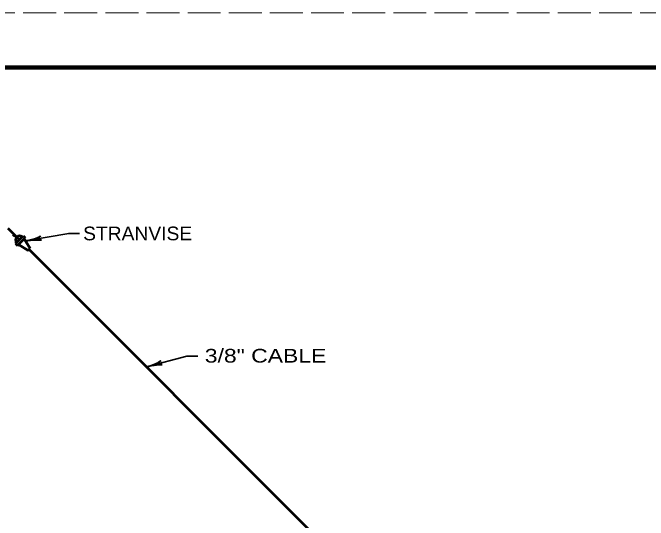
# Model space of a CAD drawing. Extents: x 12366 to 13046, y 9129 to 9570.
# Drawn here: x 12746.6 to 12862.5, y 9477.1 to 9569.5 of the extents above; entities that cross this region are included whole.
import ezdxf

# ---------------------------------------------------------------- set-up
doc = ezdxf.new("R2010")
doc.units = 0
doc.linetypes.add('LONG_DASHED', pattern=[7.5, 6, -1.5])
doc.layers.add('1', color=7, linetype='Continuous', lineweight=53)
doc.layers.add('61', color=7, linetype='Continuous', lineweight=35)

msp = doc.modelspace()

# ---------------------------------------------------------------- linework, layer by layer
at = {"layer": '1'}
for p, q in [((12745.687, 9530.302), (12747.808, 9528.181)), ((12747.324, 9528.665), (12746.62, 9529.072)), ((12747.101, 9527.474), (12748.515, 9528.888)), ((12747.455, 9527.12), (12748.869, 9528.534)), ((12748.515, 9528.888), (12748.869, 9528.534)), ((12748.692, 9528.358), (12749.753, 9526.59)), ((12747.101, 9527.474), (12747.455, 9527.12)), ((12747.631, 9527.297), (12749.399, 9526.236)), ((12749.399, 9526.236), (12749.753, 9526.59)), ((12749.576, 9526.413), (12810.747, 9465.242))]:
    msp.add_line(p, q, dxfattribs=at)
at = {"layer": '1', "lineweight": 35}
for points in [[(12748.934, 9527.954), (12756.791, 9529.339), (12758.791, 9529.339)], [(12770.977, 9505.011), (12778.337, 9506.983), (12780.337, 9506.983)]]:
    msp.add_lwpolyline(points, dxfattribs=at)
at = {"layer": '1'}
msp.add_arc((12747.856, 9528.133), 0.753, 50.20411, 219.79589, dxfattribs=at)
at = {"layer": '1', "lineweight": 40}
for centre, major_axis, ratio, start_param, end_param in [((12749.961, 9528.416), (-1.731, -0.464), 0.122415, 0.8963533, 3.1415927), ((12750.074, 9527.94), (1.76, 0.132), 0.07063, 6.2823074, 8.5597026), ((12771.96, 9505.561), (-1.684, -0.613), 0.122415, 0.8963533, 3.1415927), ((12771.96, 9505.561), (-1.684, -0.613), 0.122415, 0.8963533, 3.1415927), ((12772.115, 9505.097), (1.742, 0.285), 0.07063, 6.2823074, 8.5597026), ((12772.115, 9505.097), (1.742, 0.285), 0.07063, 6.2823074, 8.5597026)]:
    msp.add_ellipse(centre, major_axis=major_axis, ratio=ratio, start_param=start_param, end_param=end_param, dxfattribs=at)
at = {"layer": '61', "linetype": 'LONG_DASHED', "lineweight": 13}
msp.add_line((12365.992, 9569.533), (13046.012, 9569.533), dxfattribs=at)
at = {"layer": '61', "lineweight": 158}
msp.add_lwpolyline([(13035.032, 9559.533), (12395.992, 9559.533), (12395.992, 9139.513)], dxfattribs=at)

# ---------------------------------------------------------------- texts
at = {"layer": '1'}
for s, width, p in [('STRANVISE', 1.05, (12759.42, 9528.072)), ('3/8" CABLE', 1.25, (12781.613, 9505.797))]:
    msp.add_text(s, height=2.5, dxfattribs=dict(at, width=width)).set_placement(p)

doc.saveas('drawing.dxf')
